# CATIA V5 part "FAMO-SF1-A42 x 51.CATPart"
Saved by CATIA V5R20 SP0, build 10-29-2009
Part number: FAMO-SF1-A42 x 51
Definition: NONE
Nomenclature: FAMO-SF1-A42 x 51
Source: Unknown
Description: FAMO-SF1-A42 x 51
Bounding box of the stored display mesh (mm): x -13 to 38, y -31.5 to 31.5, z -31.5 to 31.5
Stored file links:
  C:\Users\Utente\Desktop\IO LAVORO\3D X SITO CF\X SITO\FAMO\FAMO-SF1-A42 x 51.CATPart
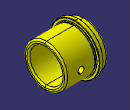
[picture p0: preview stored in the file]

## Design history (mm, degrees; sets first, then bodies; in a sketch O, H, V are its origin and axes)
Body1 "FAMO-SF1-A42 x 51" (main body)
  Solid1: solid without history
